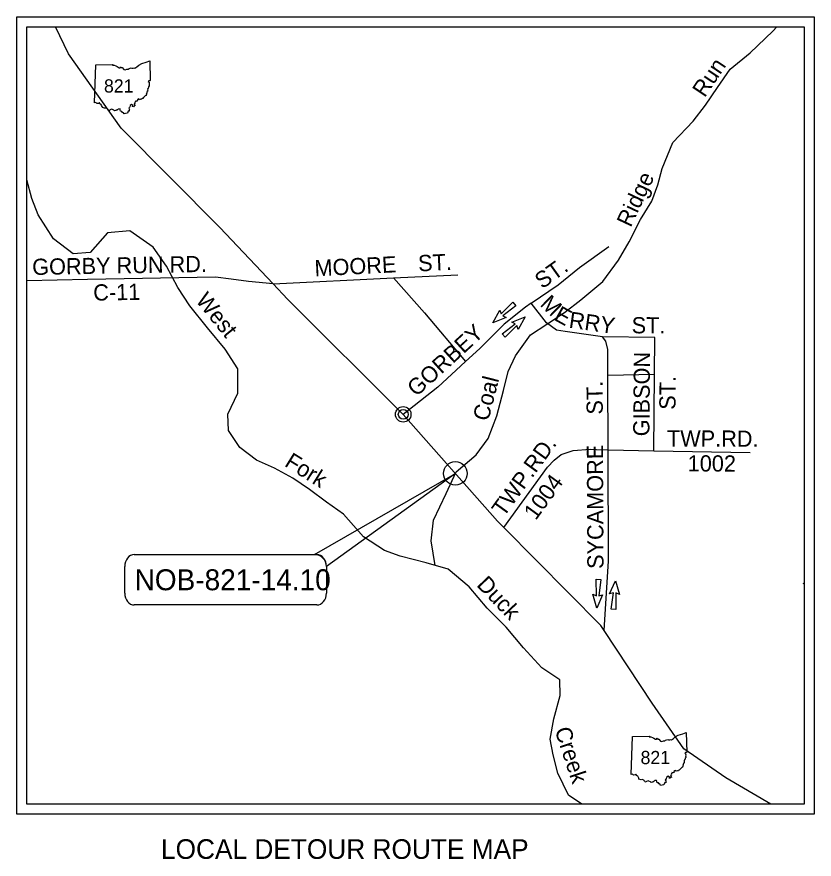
# Model space of a CAD drawing. Extents: x -452339 to 6403467, y -1 to 1814750.
# Drawn here: x -295911 to -255417, y 1582215 to 1624994 of the extents above; entities that cross this region are included whole.
import ezdxf

# ---------------------------------------------------------------- set-up
doc = ezdxf.new("R2010")
doc.units = 0
for name, color, linetype in [('Default', 7, 'Continuous'), ('GM_X_Adjacent_County', 7, 'Continuous'), ('GM_X_County', 7, 'Continuous'), ('GM_X_County_Road', 7, 'Continuous'), ('GM_X_County_Road_Text', 7, 'Continuous'), ('GM_X_Section', 7, 'Continuous'), ('GM_X_Township', 7, 'Continuous'), ('GM_X_Township_Road_Text', 7, 'Continuous'), ('GM_X_Township_ROW', 7, 'Continuous')]:
    doc.layers.add(name, color=color, linetype=linetype)

msp = doc.modelspace()

# ---------------------------------------------------------------- linework, layer by layer
at = {"layer": 'Default'}
for p, q in [((-295411, 1585000), (-295411, 1624494)), ((-295411, 1624494), (-255917, 1624494)), ((-255917, 1624494), (-255917, 1585000)), ((-291959, 1620619), (-291897, 1622556)), ((-271314, 1609905), (-270728, 1610498)), ((-270572, 1610320), (-271235, 1609815)), ((-270728, 1610498), (-270572, 1610320)), ((-271740, 1609450), (-271384, 1610094)), ((-271384, 1610094), (-271314, 1609905)), ((-271235, 1609815), (-271056, 1609721)), ((-271056, 1609721), (-271740, 1609450)), ((-271259, 1608897), (-270595, 1609402)), ((-270774, 1609495), (-270091, 1609766)), ((-270595, 1609402), (-270774, 1609495)), ((-270091, 1609766), (-270447, 1609122)), ((-270516, 1609311), (-271102, 1608719)), ((-270447, 1609122), (-270516, 1609311)), ((-271102, 1608719), (-271259, 1608897)), ((-266476, 1595593), (-266480, 1596427)), ((-266480, 1596427), (-266244, 1596410)), ((-266244, 1596410), (-266358, 1595585)), ((-265805, 1595683), (-265512, 1596357)), ((-265512, 1596357), (-265310, 1595650)), ((-265613, 1595743), (-265805, 1595683)), ((-265726, 1594917), (-265613, 1595743)), ((-265310, 1595650), (-265493, 1595735)), ((-265493, 1595735), (-265490, 1594901)), ((-266458, 1594970), (-266660, 1595677)), ((-266660, 1595677), (-266476, 1595593)), ((-266164, 1595645), (-266458, 1594970)), ((-266358, 1595585), (-266164, 1595645)), ((-265490, 1594901), (-265726, 1594917)), ((-264707, 1586510), (-264645, 1588446)), ((-255917, 1585000), (-295411, 1585000))]:
    msp.add_line(p, q, dxfattribs=at)
msp.add_lwpolyline([(-255417, 1584500), (-295911, 1584500), (-295911, 1624994), (-255417, 1624994)], close=True, dxfattribs=at)
for points in [[(-291897, 1622556), (-291038, 1622568), (-291051, 1622544), (-290971, 1622540), (-290885, 1622498), (-290812, 1622472), (-290723, 1622411), (-290670, 1622411), (-290647, 1622462), (-290606, 1622423), (-290558, 1622416), (-290474, 1622323), (-290405, 1622303), (-290322, 1622335), (-290261, 1622340), (-290215, 1622372), (-290097, 1622399), (-290064, 1622382), (-290002, 1622386), (-289970, 1622398), (-289916, 1622387), (-289821, 1622458), (-289722, 1622540), (-289570, 1622619), (-289344, 1622693), (-289164, 1622759), (-289139, 1621754)], [(-289139, 1621754), (-289165, 1621740), (-289206, 1621747), (-289234, 1621719), (-289199, 1621672), (-289183, 1621622), (-289198, 1621567), (-289183, 1621522), (-289193, 1621484), (-289219, 1621446), (-289228, 1621411), (-289250, 1621373), (-289248, 1621352), (-289269, 1621335), (-289265, 1621272), (-289276, 1621237), (-289272, 1621207), (-289306, 1621200), (-289298, 1621175), (-289320, 1621155), (-289315, 1621122), (-289340, 1621101), (-289316, 1621059), (-289335, 1621046), (-289351, 1620994), (-289395, 1620984), (-289482, 1620891), (-289513, 1620855), (-289547, 1620846), (-289567, 1620810), (-289609, 1620810), (-289674, 1620784), (-289716, 1620828), (-289788, 1620775), (-289797, 1620715), (-289889, 1620717), (-289886, 1620686), (-289906, 1620678), (-289925, 1620647), (-289914, 1620593), (-289957, 1620579), (-289952, 1620547), (-289924, 1620528), (-289912, 1620468), (-289958, 1620480), (-289995, 1620429), (-290035, 1620441), (-290022, 1620484), (-290087, 1620536), (-290149, 1620495), (-290181, 1620428), (-290182, 1620383), (-290228, 1620356), (-290198, 1620294), (-290204, 1620250), (-290203, 1620209), (-290261, 1620210), (-290296, 1620099)], [(-290296, 1620099), (-290396, 1620078), (-290465, 1620065), (-290490, 1620116), (-290539, 1620143), (-290572, 1620193), (-290643, 1620200), (-290660, 1620270), (-290668, 1620326), (-290766, 1620313), (-290792, 1620278), (-290827, 1620269), (-290847, 1620234), (-290895, 1620231), (-290945, 1620214), (-290979, 1620248), (-291061, 1620283), (-291099, 1620301), (-291177, 1620273), (-291193, 1620241), (-291255, 1620255), (-291270, 1620291), (-291308, 1620302), (-291316, 1620341), (-291396, 1620362), (-291458, 1620353), (-291566, 1620384), (-291573, 1620435), (-291610, 1620497), (-291629, 1620540), (-291697, 1620572), (-291711, 1620623), (-291733, 1620622), (-291753, 1620601), (-291830, 1620592), (-291860, 1620612), (-291903, 1620648), (-291959, 1620619)], [(-269795, 1610449), (-270069, 1610251), (-271163, 1609379), (-272402, 1608151), (-273118, 1607487), (-274532, 1606178), (-276288, 1604806)], [(-266081, 1593821), (-265856, 1597366), (-265881, 1603009), (-265898, 1606772), (-265904, 1608106), (-266003, 1608522), (-266165, 1608745), (-268055, 1609019), (-268504, 1609079), (-269019, 1609460), (-269795, 1610449)], [(-255917, 1596224), (-255994, 1596203)], [(-264645, 1588446), (-263786, 1588459), (-263800, 1588435), (-263719, 1588431), (-263633, 1588389), (-263560, 1588363), (-263471, 1588302), (-263418, 1588302), (-263395, 1588353), (-263355, 1588314), (-263306, 1588307), (-263222, 1588214), (-263153, 1588194), (-263070, 1588226), (-263009, 1588231), (-262963, 1588262), (-262846, 1588289), (-262812, 1588273), (-262750, 1588277), (-262718, 1588288), (-262664, 1588278), (-262569, 1588348), (-262470, 1588431), (-262318, 1588510), (-262092, 1588584), (-261913, 1588650), (-261887, 1587645)], [(-261887, 1587645), (-261913, 1587631), (-261954, 1587637), (-261982, 1587610), (-261947, 1587563), (-261932, 1587513), (-261946, 1587458), (-261932, 1587413), (-261941, 1587375), (-261967, 1587337), (-261976, 1587301), (-261998, 1587264), (-261996, 1587242), (-262017, 1587226), (-262013, 1587163), (-262024, 1587128), (-262020, 1587098), (-262055, 1587090), (-262047, 1587065), (-262068, 1587046), (-262064, 1587013), (-262088, 1586992), (-262065, 1586950), (-262084, 1586936), (-262099, 1586885), (-262143, 1586875), (-262230, 1586781), (-262261, 1586746), (-262295, 1586737), (-262315, 1586700), (-262357, 1586700), (-262422, 1586675), (-262464, 1586718), (-262537, 1586666), (-262545, 1586606), (-262637, 1586608), (-262634, 1586577), (-262654, 1586568), (-262673, 1586538), (-262662, 1586483), (-262706, 1586469), (-262700, 1586438), (-262672, 1586419), (-262660, 1586359), (-262706, 1586371), (-262744, 1586320), (-262783, 1586332), (-262770, 1586375), (-262835, 1586427), (-262897, 1586385), (-262929, 1586319), (-262930, 1586274), (-262976, 1586247), (-262946, 1586184), (-262952, 1586141), (-262951, 1586099), (-263009, 1586101), (-263044, 1585990)], [(-263044, 1585990), (-263144, 1585969), (-263213, 1585956), (-263238, 1586006), (-263287, 1586033), (-263320, 1586084), (-263391, 1586091), (-263408, 1586161), (-263416, 1586217), (-263514, 1586203), (-263540, 1586169), (-263575, 1586159), (-263595, 1586124), (-263643, 1586122), (-263693, 1586105), (-263727, 1586139), (-263810, 1586174), (-263847, 1586191), (-263925, 1586164), (-263942, 1586131), (-264003, 1586146), (-264018, 1586182), (-264056, 1586193), (-264064, 1586231), (-264144, 1586252), (-264206, 1586244), (-264314, 1586275), (-264321, 1586326), (-264358, 1586388), (-264377, 1586431), (-264445, 1586463), (-264460, 1586514), (-264481, 1586513), (-264501, 1586492), (-264578, 1586482), (-264608, 1586503), (-264651, 1586539), (-264707, 1586510)]]:
    msp.add_lwpolyline(points, dxfattribs=at)
msp.add_circle((-273639, 1601805), 599, dxfattribs=at)
at = {"layer": 'GM_X_County_Road'}
msp.add_lwpolyline([(-257617, 1585000), (-259907, 1586344), (-262028, 1587810), (-263640, 1590144), (-266081, 1593821), (-266252, 1594079), (-271181, 1599060), (-271497, 1599380), (-276288, 1604806), (-282167, 1610656), (-282893, 1611426), (-285595, 1614297), (-290616, 1619343), (-293291, 1623117), (-293941, 1624494)], dxfattribs=at)
at = {"layer": 'GM_X_County_Road_Text'}
for radius in [393, 249]:
    msp.add_circle((-276288, 1604806), radius, dxfattribs=at)
at = {"layer": 'GM_X_Section'}
msp.add_lwpolyline([(-282893, 1611426), (-284154, 1611550), (-285020, 1611663), (-285822, 1611777), (-292316, 1611660), (-295411, 1611586)], dxfattribs=at)
at = {"layer": 'GM_X_Township'}
for points in [[(-269795, 1610449), (-268425, 1611388), (-267343, 1612262), (-265847, 1613332)], [(-282893, 1611426), (-276778, 1611731), (-273518, 1611893)], [(-276778, 1611731), (-275200, 1609956), (-273118, 1607487)], [(-263561, 1602945), (-263525, 1606829), (-263508, 1608702), (-266165, 1608745)], [(-263525, 1606829), (-265898, 1606772)], [(-271181, 1599060), (-268964, 1602119), (-268615, 1602474), (-268265, 1602765), (-267658, 1602963), (-266795, 1603034), (-266486, 1603025)], [(-266486, 1603025), (-266470, 1603025), (-265881, 1603009), (-263561, 1602945), (-258672, 1602871)]]:
    msp.add_lwpolyline(points, dxfattribs=at)
at = {"layer": 'GM_X_Township_Road_Text'}
for points in [[(-274670, 1597130), (-274874, 1598381), (-274749, 1599438), (-274113, 1600786), (-273605, 1601878), (-272584, 1602746), (-271979, 1603581), (-271535, 1604736), (-271187, 1606019), (-270966, 1606981), (-270584, 1607783), (-269820, 1608843), (-268990, 1609391), (-268096, 1609971), (-267266, 1610614), (-266150, 1611548), (-265353, 1612640), (-264812, 1613571), (-264240, 1614694), (-263667, 1615626), (-263350, 1616460), (-263129, 1617293), (-262589, 1618609), (-261569, 1619702), (-260931, 1620505), (-260326, 1621404), (-259689, 1622336), (-258668, 1623172), (-257520, 1624266), (-257308, 1624494)], [(-280190, 1600349), (-281055, 1600986), (-281889, 1601560), (-282818, 1602069), (-283747, 1602483), (-284581, 1603121), (-285159, 1603984), (-285193, 1604817), (-284685, 1605876), (-284689, 1607125), (-285332, 1608116), (-286230, 1609202), (-287129, 1610321), (-287740, 1611248), (-288319, 1612335), (-288994, 1613294), (-290180, 1614123), (-291299, 1614023), (-292192, 1613027), (-293055, 1612960), (-294049, 1613725), (-294821, 1614940), (-295143, 1615772), (-295411, 1616716)], [(-267208, 1585000), (-267893, 1585461), (-268440, 1586581), (-268667, 1587509), (-268829, 1588309), (-268641, 1589335), (-268324, 1590522), (-268327, 1591323), (-269256, 1591928), (-270187, 1592950), (-271054, 1594005), (-272016, 1594962), (-272947, 1596048), (-274006, 1596942), (-275126, 1597258), (-276439, 1597606), (-277239, 1597892), (-278297, 1598593), (-279324, 1599743), (-280190, 1600349)]]:
    msp.add_lwpolyline(points, dxfattribs=at)
at = {"layer": 'GM_X_Township_ROW'}
for p, q in [((-280789, 1597684), (-273639, 1601805)), ((-273639, 1601805), (-280189, 1597084))]:
    msp.add_line(p, q, dxfattribs=at)
for points in [[(-289949, 1597684), (-280669, 1597684)], [(-290429, 1595724), (-290429, 1597084)], [(-280189, 1597084), (-280189, 1595724)], [(-280669, 1595124), (-289949, 1595124)]]:
    msp.add_lwpolyline(points, dxfattribs=at)
msp.add_arc((-280789, 1597084), 600, 360, 90, dxfattribs=at)
for centre, major_axis, start_param, end_param in [((-289949, 1597084), (0, -600), 3.141593, 4.712389), ((-280669, 1597084), (0, 600), 4.712389, 6.283185), ((-289949, 1595724), (0, -600), 4.712389, 6.283185), ((-280669, 1595724), (0, 600), 3.141593, 4.712389)]:
    msp.add_ellipse(centre, major_axis=major_axis, ratio=0.8, start_param=start_param, end_param=end_param, dxfattribs=at)

# ---------------------------------------------------------------- texts
at = {"layer": 'Default'}
for s, height, p in [('821', 671.6, (-291486, 1621149)), ('821', 671.6, (-264234, 1587040)), ('LOCAL DETOUR ROUTE MAP', 997.23, (-288591, 1582229))]:
    msp.add_text(s, height=height, dxfattribs=at).set_placement(p)
at = {"layer": 'GM_X_Adjacent_County'}
for s, height, rotation, p in [('MOORE', 823.7, 2.851, (-280774, 1611815)), ('ST.', 823.7, 2.851, (-275513, 1612063)), ('ST.', 823.7, 35.569, (-269228, 1611147)), ('M', 824, 315.7646, (-269382, 1610357)), ('E', 824, 331.1434, (-268684, 1609628)), ('RRY', 823.7, 351.9497, (-267904, 1609213)), ('GORBEY', 823.7, 42.3998, (-275621, 1605667)), ('ST.', 823.7, 359.7998, (-264687, 1608921)), ('GIBSON', 823.7, 89.4761, (-263787, 1603688)), ('ST.', 823.7, 90.2552, (-266150, 1604795)), ('ST.', 823.7, 89.4761, (-262459, 1605036)), ('TWP.RD.', 823.7, 359.7998, (-262893, 1603173)), ('TWP.RD.', 823.7, 54.0679, (-271183, 1599553)), ('SYCAMORE', 823.7, 90.2552, (-266113, 1596957)), ('1002', 823.7, 359.7998, (-261841, 1601906)), ('1004', 823.7, 54.0679, (-269559, 1599387))]:
    msp.add_text(s, height=height, rotation=rotation, dxfattribs=at).set_placement(p)
at = {"layer": 'GM_X_County'}
for s, height, p in [('GORBY RUN RD.', 823.68, (-295124, 1611881)), ('C-11', 823.7, (-292025, 1610579))]:
    msp.add_text(s, height=height, rotation=1.029, dxfattribs=at).set_placement(p)
at = {"layer": 'GM_X_Township_Road_Text'}
for s, rotation, p in [('Run', 56.2782, (-260977, 1620857)), ('Ridge', 64.7386, (-264738, 1614265)), ('West', 309.0639, (-286864, 1610578)), ('Coal', 75.7813, (-271967, 1604420)), ('Fork', 328.0674, (-282365, 1602207)), ('Duck', 313.6113, (-272599, 1596116)), ('Creek', 288.199, (-268606, 1588779))]:
    msp.add_text(s, height=823.7, rotation=rotation, dxfattribs=at).set_placement(p)
at = {"layer": 'GM_X_Township_ROW'}
msp.add_text('NOB-821-14.10', height=1063.82, dxfattribs=at).set_placement((-289932, 1595872))

doc.saveas('drawing.dxf')
